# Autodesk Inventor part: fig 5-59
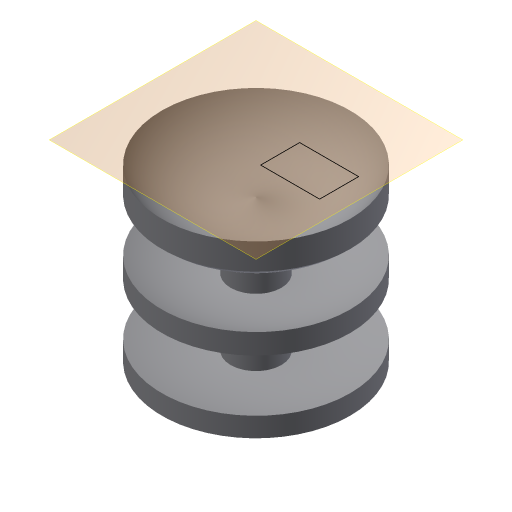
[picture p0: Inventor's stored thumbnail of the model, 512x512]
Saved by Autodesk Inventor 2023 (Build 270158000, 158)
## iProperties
Created: 2004-05
Part Number: fig 5-59
Document SubType Name: Modeling
Designer: CADCIM Technologies
Manufacturer: Standard
Standards Organization: Custom
Density: 1 g/cm^3
Material: Generic
Appearance: Default
Author: CADCIM Technologies
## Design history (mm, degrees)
sketch "Sketch1"
  geometry: L1 (0.098, 22.743)-(0.098, 0.516); L2 (-3.621, 19.305)-(-3.621, 13.061); L3 (-3.621, 10.379)-(-3.621, 3.25); L4 (-3.664, 0.516)-(0.098, 0.516); L5 (-13.694, 4.7)-(-13.694, 1.836); L6 (-13.694, 26.851)-(-13.694, 23.014); L7 (-13.694, 15.335)-(-13.694, 12.343); A1 r 10.546 centre (-4.597, 32.185) between (-13.694, 26.851) and (0.098, 22.743); A2 r 21.828 centre (-4.597, 32.185) between (-13.694, 12.343) and (-3.621, 10.379); A3 r 12.918 centre (-4.597, 32.185) between (-13.694, 23.014) and (-3.621, 19.305); A4 r 19.149 centre (-4.597, 32.185) between (-13.694, 15.335) and (-3.621, 13.061); A5 r 28.952 centre (-4.597, 32.185) between (-13.694, 4.7) and (-3.621, 3.25); A6 r 31.683 centre (-4.597, 32.185) between (-13.694, 1.836) and (-3.664, 0.516)
  constraints: 14 end point, 12 point on circle, 6 centre point, 4 perpendicular, 2 parallel, 1 vertical
revolve "Revolution1" sketch "Sketch1" stored, may be unused: angle "d0" = 90 deg
workplane "Work Plane1"
sketch "Sketch2"
  geometry: L1 (3.408, -2.846)-(12.06, -2.846); L2 (12.06, -2.846)-(12.06, 2.873); L3 (12.06, 2.873)-(3.408, 2.873); L4 (3.408, 2.873)-(3.408, -2.846)
  constraints: 8 end point, 2 parallel, 1 horizontal, 1 perpendicular
body "Solid1"
